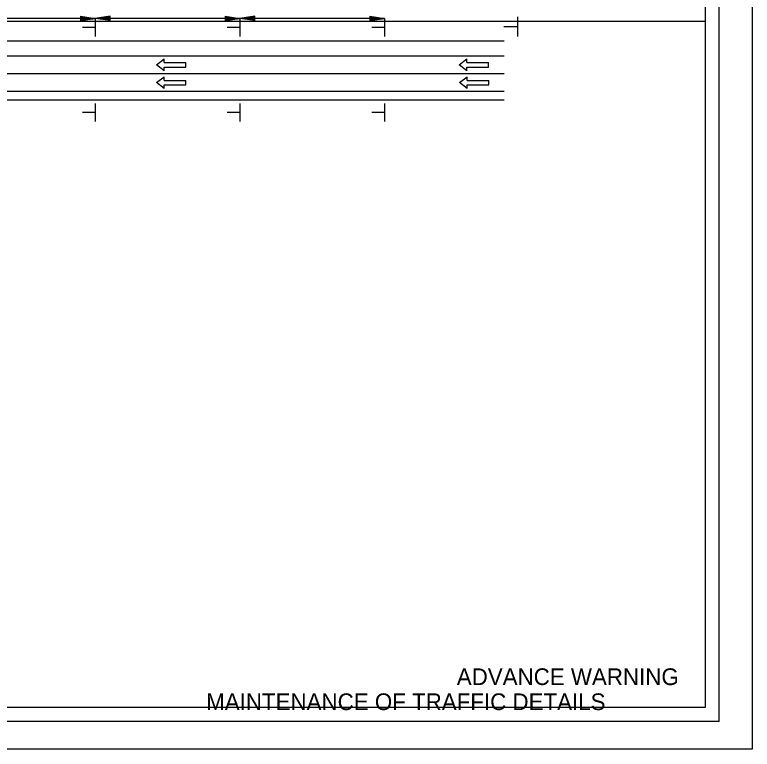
# Model space of a CAD drawing. Extents: x -500 to 213, y 382723 to 382830.
# Drawn here: x -386.5 to -333.5, y 382723.1 to 382775.9 of the extents above; entities that cross this region are included whole.
import ezdxf

# ---------------------------------------------------------------- set-up
doc = ezdxf.new("R2010")
doc.units = 0
for name, color, linetype in [('Default', 7, 'Continuous'), ('R_Border', 7, 'Continuous'), ('R_Border Title', 7, 'Continuous'), ('R_Draft', 7, 'Continuous'), ('R_MOT', 7, 'Continuous'), ('R_No Plot', 7, 'Continuous')]:
    doc.layers.add(name, color=color, linetype=linetype)

msp = doc.modelspace()

# ---------------------------------------------------------------- linework, layer by layer
at = {"layer": 'Default'}
for p, q in [((-380.757, 382775.68), (-389.854, 382775.68)), ((-370.357, 382775.68), (-380.757, 382775.68)), ((-359.957, 382775.68), (-370.357, 382775.68)), ((-351.369, 382774.032), (-410.08, 382774.032)), ((-351.369, 382772.973), (-410.08, 382772.973)), ((-376.369, 382772.34), (-375.819, 382772.764)), ((-375.819, 382772.499), (-375.819, 382772.764)), ((-354.595, 382772.34), (-354.045, 382772.764)), ((-354.045, 382772.499), (-354.045, 382772.764)), ((-375.819, 382771.916), (-376.369, 382772.34)), ((-375.819, 382772.499), (-374.261, 382772.499)), ((-375.819, 382772.181), (-374.261, 382772.181)), ((-375.819, 382771.916), (-375.819, 382772.181)), ((-374.261, 382772.181), (-374.261, 382772.499)), ((-354.045, 382771.916), (-354.595, 382772.34)), ((-354.045, 382772.499), (-352.486, 382772.499)), ((-354.045, 382772.181), (-352.486, 382772.181)), ((-354.045, 382771.916), (-354.045, 382772.181)), ((-352.486, 382772.181), (-352.486, 382772.499)), ((-351.369, 382771.702), (-410.08, 382771.702)), ((-376.361, 382771.058), (-375.811, 382771.481)), ((-375.811, 382771.217), (-375.811, 382771.481)), ((-375.811, 382771.217), (-374.252, 382771.217)), ((-374.252, 382770.899), (-374.252, 382771.217)), ((-354.586, 382771.058), (-354.036, 382771.481)), ((-354.036, 382771.217), (-354.036, 382771.481)), ((-354.036, 382771.217), (-352.478, 382771.217)), ((-352.478, 382770.899), (-352.478, 382771.217)), ((-375.811, 382770.634), (-376.361, 382771.058)), ((-375.811, 382770.899), (-374.252, 382770.899)), ((-375.811, 382770.634), (-375.811, 382770.899)), ((-354.036, 382770.634), (-354.586, 382771.058)), ((-354.036, 382770.899), (-352.478, 382770.899)), ((-354.036, 382770.634), (-354.036, 382770.899)), ((-351.369, 382770.43), (-410.08, 382770.43)), ((-351.369, 382769.795), (-410.08, 382769.795))]:
    msp.add_line(p, q, dxfattribs=at)
at = {"layer": 'R_Border'}
for q in [(-335.908, 382827.85), (-493.998, 382725.12)]:
    msp.add_line((-335.908, 382725.12), q, dxfattribs=at)
at = {"layer": 'R_Draft'}
for p, q in [((-381.816, 382775.839), (-380.757, 382775.68)), ((-381.816, 382775.839), (-381.816, 382775.521)), ((-381.816, 382775.813), (-380.934, 382775.68)), ((-381.816, 382775.786), (-381.116, 382775.68)), ((-381.816, 382775.759), (-381.292, 382775.68)), ((-381.816, 382775.732), (-381.472, 382775.68)), ((-381.816, 382775.705), (-381.649, 382775.68)), ((-381.816, 382775.521), (-380.757, 382775.68)), ((-381.816, 382775.628), (-381.472, 382775.68)), ((-381.816, 382775.575), (-381.116, 382775.68)), ((-381.816, 382775.548), (-380.934, 382775.68)), ((-381.816, 382775.601), (-381.292, 382775.68)), ((-381.816, 382775.656), (-381.649, 382775.68)), ((-379.698, 382775.839), (-380.757, 382775.68)), ((-379.698, 382775.521), (-380.757, 382775.68)), ((-379.698, 382775.813), (-380.58, 382775.68)), ((-379.698, 382775.548), (-380.58, 382775.68)), ((-379.698, 382775.786), (-380.398, 382775.68)), ((-379.698, 382775.575), (-380.398, 382775.68)), ((-379.698, 382775.759), (-380.221, 382775.68)), ((-379.698, 382775.601), (-380.221, 382775.68)), ((-379.698, 382775.732), (-380.042, 382775.68)), ((-379.698, 382775.629), (-380.042, 382775.68)), ((-379.698, 382775.705), (-379.865, 382775.68)), ((-379.698, 382775.656), (-379.865, 382775.68)), ((-379.698, 382775.521), (-379.698, 382775.839)), ((-371.416, 382775.839), (-370.357, 382775.68)), ((-371.416, 382775.839), (-371.416, 382775.521)), ((-371.416, 382775.813), (-370.534, 382775.68)), ((-371.416, 382775.786), (-370.716, 382775.68)), ((-371.416, 382775.759), (-370.893, 382775.68)), ((-371.416, 382775.732), (-371.072, 382775.68)), ((-371.416, 382775.705), (-371.249, 382775.68)), ((-371.416, 382775.521), (-370.357, 382775.68)), ((-371.416, 382775.628), (-371.072, 382775.68)), ((-371.416, 382775.575), (-370.716, 382775.68)), ((-371.416, 382775.548), (-370.534, 382775.68)), ((-371.416, 382775.601), (-370.893, 382775.68)), ((-371.416, 382775.656), (-371.249, 382775.68)), ((-369.298, 382775.839), (-370.357, 382775.68)), ((-369.298, 382775.521), (-370.357, 382775.68)), ((-369.298, 382775.813), (-370.18, 382775.68)), ((-369.298, 382775.548), (-370.18, 382775.68)), ((-369.298, 382775.786), (-369.998, 382775.68)), ((-369.298, 382775.575), (-369.998, 382775.68)), ((-369.298, 382775.759), (-369.822, 382775.68)), ((-369.298, 382775.601), (-369.822, 382775.68)), ((-369.298, 382775.732), (-369.642, 382775.68)), ((-369.298, 382775.629), (-369.642, 382775.68)), ((-369.298, 382775.705), (-369.465, 382775.68)), ((-369.298, 382775.656), (-369.465, 382775.68)), ((-369.298, 382775.521), (-369.298, 382775.839)), ((-361.017, 382775.839), (-359.957, 382775.68)), ((-361.017, 382775.839), (-361.017, 382775.521)), ((-361.017, 382775.813), (-360.134, 382775.68)), ((-361.017, 382775.786), (-360.316, 382775.68)), ((-361.017, 382775.759), (-360.493, 382775.68)), ((-361.017, 382775.732), (-360.672, 382775.68)), ((-361.017, 382775.705), (-360.849, 382775.68)), ((-361.017, 382775.521), (-359.957, 382775.68)), ((-361.017, 382775.628), (-360.672, 382775.68)), ((-361.017, 382775.575), (-360.316, 382775.68)), ((-361.017, 382775.548), (-360.134, 382775.68)), ((-361.017, 382775.601), (-360.493, 382775.68)), ((-361.017, 382775.656), (-360.849, 382775.68))]:
    msp.add_line(p, q, dxfattribs=at)
at = {"layer": 'R_MOT'}
for p, q in [((-380.757, 382775.68), (-380.757, 382774.371)), ((-370.357, 382775.68), (-370.357, 382774.371)), ((-359.957, 382775.68), (-359.957, 382774.371)), ((-350.409, 382775.779), (-350.403, 382774.377)), ((-380.776, 382775.029), (-381.669, 382775.029)), ((-370.376, 382775.029), (-371.269, 382775.029)), ((-359.976, 382775.029), (-360.87, 382775.029)), ((-350.406, 382775.081), (-351.383, 382775.077)), ((-380.757, 382769.562), (-380.757, 382768.253)), ((-370.357, 382769.562), (-370.357, 382768.253)), ((-359.957, 382769.562), (-359.957, 382768.253)), ((-380.776, 382768.911), (-381.669, 382768.91)), ((-370.376, 382768.911), (-371.269, 382768.91)), ((-359.976, 382768.911), (-360.87, 382768.91))]:
    msp.add_line(p, q, dxfattribs=at)
at = {"layer": 'R_No Plot'}
for points in [[(-500.202, 382829.798), (-333.532, 382829.798), (-333.532, 382723.129), (-500.202, 382723.129)], [(-492.998, 382826.85), (-368.228, 382826.85), (-368.228, 382821.91), (-359.458, 382821.91), (-347.408, 382821.91), (-347.408, 382810.744), (-336.908, 382810.744), (-336.908, 382726.12), (-492.998, 382726.12)], [(-492.998, 382775.485), (-336.908, 382775.485), (-336.908, 382726.12), (-492.998, 382726.12)]]:
    msp.add_lwpolyline(points, close=True, dxfattribs=at)

# ---------------------------------------------------------------- texts
at = {"layer": 'R_Border Title'}
for s, p in [('ADVANCE WARNING', (-354.772, 382727.745)), ('MAINTENANCE OF TRAFFIC DETAILS', (-372.788, 382725.945))]:
    msp.add_text(s, height=1.2, dxfattribs=at).set_placement(p)

doc.saveas('drawing.dxf')
